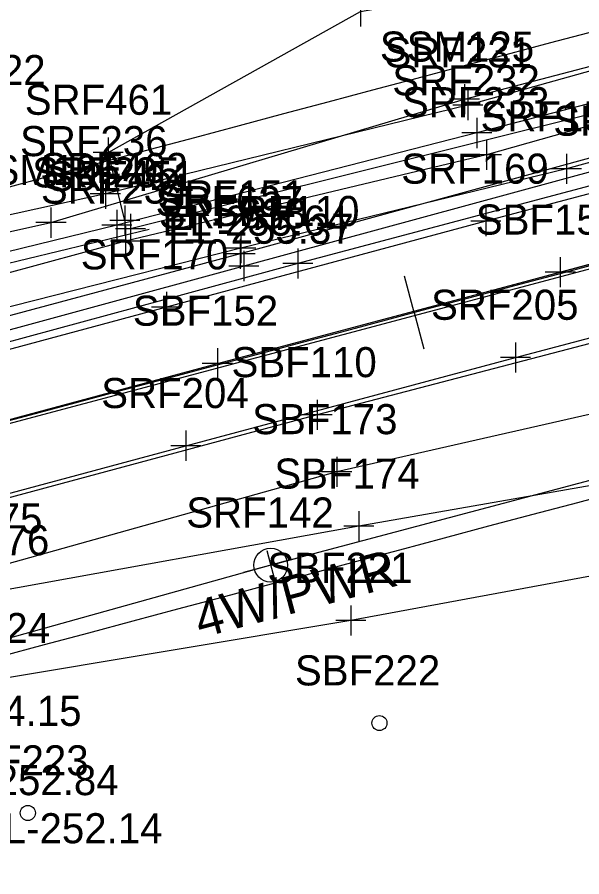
# Model space of a CAD drawing. Extents: x 818717 to 846077, y 440014 to 541392.
# Drawn here: x 831874.2 to 831949.3, y 493090.2 to 493204.5 of the extents above; entities that cross this region are included whole.
import ezdxf

# ---------------------------------------------------------------- set-up
doc = ezdxf.new("R2010")
doc.units = 0
for name, color, linetype in [('SURVEY - CENTERLINE - Preliminary', 7, 'Continuous'), ('SURVEY - CENTERLINE - Preliminary Text', 7, 'Continuous'), ('SURVEY - DRAINAGE - Area Shapes', 7, 'Continuous'), ('SURVEY - DRAINAGE - Natural Features Text', 7, 'Continuous'), ('SURVEY - DTM - Breaklines', 7, 'Continuous'), ('SURVEY - DTM - Breaklines - Points - Elevations', 7, 'Continuous'), ('SURVEY - DTM - Breaklines - Points - Locators', 7, 'Continuous'), ('SURVEY - DTM - Breaklines - Points - Numbers', 7, 'Continuous'), ('SURVEY - DTM - Spot Points - Locators', 7, 'Continuous'), ('SURVEY - DTM - Spot Points - Point Numbers', 7, 'Continuous'), ('SURVEY - PROPERTY - ROW Lines', 7, 'Continuous'), ('SURVEY - TRAFFIC CONTROL - Pavement Marking - Points - Locators', 7, 'Continuous'), ('SURVEY - TRAFFIC CONTROL - Pavement Marking - Points - Numbers', 7, 'Continuous'), ('SURVEY - TRAFFIC CONTROL - Pavement Marking with Text', 7, 'Continuous'), ('SURVEY - TRANSPORTATION - Features - Points - Elevations', 7, 'Continuous'), ('SURVEY - TRANSPORTATION - Roads', 7, 'Continuous'), ('SURVEY - TRANSPORTATION - Roads - Points - Locators', 7, 'Continuous'), ('SURVEY - TRANSPORTATION - Roads - Points - Numbers', 7, 'Continuous'), ('SURVEY - UTILITIES - Electric (Overhead) with Text', 7, 'Continuous'), ('SURVEY - UTILITIES - Poles and Miscellaneous - Points - Locators', 7, 'Continuous'), ('SURVEY - UTILITIES - Poles and Miscellaneous - Points - Numbers', 7, 'Continuous'), ('SURVEY - UTILITIES - Poles and Miscellaneous with Text', 7, 'Continuous'), ('SURVEY - UTILITIES - Telephone (Underground) - Points - Locators', 7, 'Continuous'), ('SURVEY - UTILITIES - Telephone (Underground) - Points - Numbers', 7, 'Continuous'), ('SURVEY - UTILITIES - Telephone (Underground) with Text', 7, 'Continuous'), ('SURVEY - UTILITIES - Water - Points - Locators', 7, 'Continuous'), ('SURVEY - UTILITIES - Water - Points - Numbers', 7, 'Continuous'), ('SURVEY - UTILITIES - Water with Text', 7, 'Continuous'), ('SURVEY - VEGETATION - Features - Points - Elevations', 7, 'Continuous'), ('SURVEY - VEGETATION - Features - Points - Locators', 7, 'Continuous'), ('SURVEY - VEGETATION - Features - Points - Numbers', 7, 'Continuous'), ('SURVEY - VEGETATION - Features with Text', 7, 'Continuous')]:
    doc.layers.add(name, color=color, linetype=linetype)

msp = doc.modelspace()

# ---------------------------------------------------------------- linework, layer by layer
at = {"layer": 'SURVEY - CENTERLINE - Preliminary'}
msp.add_arc((846074.62, 440015.93), 55000, 104.635499, 105.043654, dxfattribs=at)
msp.add_arc((846074.62, 440015.93), 55000, 104.635499, 105.043654, dxfattribs=at)
msp.add_arc((846074.62, 440015.93), 55000, 104.635499, 105.043654, dxfattribs=at)
at = {"layer": 'SURVEY - CENTERLINE - Preliminary Text'}
for p, q in [((831940, 493168.86), (831988.29, 493181.84)), ((831927.05, 493165.22), (831925.77, 493170.05)), ((831927.05, 493165.22), (831928.34, 493160.39))]:
    msp.add_line(p, q, dxfattribs=at)
at = {"layer": 'SURVEY - DRAINAGE - Area Shapes'}
msp.add_lwpolyline([(833331.86, 493535.43), (832825.85, 493400.54), (832121.68, 493216.64), (831495.16, 493049.75), (830960.37, 492909.24), (830124.73, 492686.08), (830069.9, 493396.23), (830870.86, 494031.84), (831248.11, 494413.67), (831536.95, 494545.33), (832050.07, 494534.01), (832097.96, 494614.84), (832139.36, 494784.62), (832167.46, 494840.58), (832274.31, 494844.36), (832647.22, 494804.13), (832934.24, 494910.41), (833081.03, 494456.05), (833331.86, 493535.43)], dxfattribs=at)
at = {"layer": 'SURVEY - DRAINAGE - Natural Features Text'}
msp.add_line((831853.84, 493167.16), (831891.8, 493176.31), dxfattribs=at)
at = {"layer": 'SURVEY - DTM - Breaklines'}
for points in [[(831770.96, 493123.4), (831813.86, 493135.07), (831857.39, 493146.73), (831900.86, 493158.47), (831946.48, 493170.59), (831992.71, 493182.98), (832039.15, 493195.18), (832084.76, 493206.97), (832129.99, 493218.78), (832149.29, 493223.98), (832194.39, 493235.62), (832247.61, 493249.75), (832293.49, 493261.68), (832340.52, 493273.78)], [(832142.59, 493248.12), (832139.68, 493247.54), (832108.04, 493238.25), (832059.21, 493226.8), (832016.93, 493214.13), (831977.53, 493204.88), (831934.18, 493192.82), (831885.96, 493181.02), (831841.41, 493171.23), (831796.37, 493166.38), (831801.69, 493181.68), (831795.28, 493183.83), (831789.32, 493168.76), (831775.78, 493173.56), (831765.85, 493166.76)], [(832140.22, 493244.36), (832106.95, 493233.7), (832060.11, 493221.66), (832022.66, 493211.6), (831981.44, 493201.09), (831935.37, 493189.1), (831887.47, 493176.86), (831843.25, 493166.04), (831798.12, 493162.94), (831794.2, 493164.7), (831799.41, 493178.67), (831795.65, 493181.96), (831790.41, 493167.38)], [(832140.95, 493241.96), (832107.3, 493230.3), (832060.96, 493218.28), (832023.31, 493209.39), (831981.76, 493198.9), (831936.65, 493186.2), (831888.63, 493174.71), (831844.24, 493162.67), (831795, 493159.67)], [(832140.88, 493237.3), (832107.45, 493226.49), (832065.3, 493215.2), (832029.04, 493206.5), (831988.85, 493195.72), (831947.28, 493184.33), (831903.99, 493173.8), (831854.37, 493161.21), (831813.24, 493150.7), (831784.54, 493147.95), (831766.05, 493144.17), (831768.61, 493132.98)], [(832195.49, 493218.96), (832149.66, 493208), (832104.44, 493192.76), (832056.4, 493179.89), (832008.79, 493165.69), (831963, 493154.57), (831916.73, 493144.05), (831869.5, 493130.85), (831832.06, 493121.28), (831826.36, 493121.02)], [(832151.95, 493201.02), (832107.01, 493186.71), (832059.04, 493168.48), (832010.73, 493158.07), (831966.04, 493144.93), (831919.68, 493136.81), (831870.53, 493127.95), (831847.89, 493115.55), (831850.33, 493110.02), (831858.04, 493103.05), (831863.88, 493096.65)], [(832157.93, 493179.81), (832105.79, 493168.96), (832054.16, 493155.49), (832007.33, 493148.26), (831961.05, 493132.11), (831918.6, 493124.28), (831870.52, 493116.27), (831853.11, 493112.26), (831850.33, 493110.02)]]:
    msp.add_lwpolyline(points, dxfattribs=at)
at = {"layer": 'SURVEY - DTM - Breaklines - Points - Locators'}
for p, q in [((831934.18, 493194.82), (831934.18, 493190.82)), ((831936.18, 493192.82), (831932.18, 493192.82)), ((831935.37, 493191.1), (831935.37, 493187.1)), ((831937.37, 493189.1), (831933.37, 493189.1)), ((831936.65, 493188.2), (831936.65, 493184.2)), ((831938.65, 493186.2), (831934.65, 493186.2)), ((831947.28, 493186.33), (831947.28, 493182.33)), ((831949.28, 493184.33), (831945.28, 493184.33)), ((831885.96, 493183.02), (831885.96, 493179.02)), ((831887.96, 493181.02), (831883.96, 493181.02)), ((831887.47, 493178.86), (831887.47, 493174.86)), ((831889.47, 493176.86), (831885.47, 493176.86)), ((831888.63, 493176.71), (831888.63, 493172.71)), ((831903.99, 493175.8), (831903.99, 493171.8)), ((831890.63, 493174.71), (831886.63, 493174.71)), ((831905.99, 493173.8), (831901.99, 493173.8)), ((831946.48, 493172.59), (831946.48, 493168.59)), ((831948.48, 493170.59), (831944.48, 493170.59)), ((831900.86, 493160.47), (831900.86, 493156.47)), ((831902.86, 493158.47), (831898.86, 493158.47)), ((831916.73, 493146.05), (831916.73, 493142.05)), ((831918.73, 493144.05), (831914.73, 493144.05)), ((831919.68, 493138.81), (831919.68, 493134.81)), ((831921.68, 493136.81), (831917.68, 493136.81)), ((831918.6, 493126.28), (831918.6, 493122.28)), ((831920.6, 493124.28), (831916.6, 493124.28))]:
    msp.add_line(p, q, dxfattribs=at)
at = {"layer": 'SURVEY - DTM - Spot Points - Locators'}
for centre in [(831922.42, 493110.64), (831875.65, 493098.68)]:
    msp.add_circle(centre, 1, dxfattribs=at)
at = {"layer": 'SURVEY - PROPERTY - ROW Lines'}
for radius in [55030, 54970]:
    msp.add_arc((846074.62, 440015.93), radius, 104.635499, 105.043649, dxfattribs=at)
at = {"layer": 'SURVEY - TRAFFIC CONTROL - Pavement Marking - Points - Locators'}
for p, q in [((831936.58, 493179.36), (831936.58, 493175.36)), ((831938.58, 493177.36), (831934.58, 493177.36)), ((831894.1, 493167.96), (831894.1, 493163.96)), ((831896.1, 493165.96), (831892.1, 493165.96)), ((831940.52, 493161.26), (831940.52, 493157.26)), ((831942.52, 493159.26), (831938.52, 493159.26)), ((831896.65, 493149.52), (831896.65, 493145.52)), ((831898.65, 493147.52), (831894.65, 493147.52))]:
    msp.add_line(p, q, dxfattribs=at)
at = {"layer": 'SURVEY - TRAFFIC CONTROL - Pavement Marking with Text'}
for points in [[(832159.39, 493235.77), (832116.7, 493224.52), (832072.63, 493213.17), (832030, 493201.97), (831987.46, 493190.83), (831936.58, 493177.36), (831894.1, 493165.96), (831849.46, 493153.92), (831808.03, 493142.52), (831768.36, 493131.66), (831727.87, 493120.89), (831684.5, 493109.18), (831641.68, 493097.86), (831599.16, 493086.58), (831554.58, 493074.61), (831511.86, 493063.5), (831467.07, 493051.66), (831425.05, 493040.69), (831380.34, 493029.11), (831337.84, 493017.82), (831296.13, 493006.89), (831251.61, 492995.36), (831208.94, 492984.12), (831169.87, 492973.88)], [(831174.64, 492955.97), (831217.88, 492967.4), (831260.2, 492978.43), (831305.6, 492990.16), (831350.87, 493002.2), (831397.34, 493014.25), (831441.59, 493025.83), (831487.77, 493037.91), (831534.41, 493050.33), (831587.19, 493064.38), (831630.52, 493075.92), (831676.82, 493088.3), (831723.86, 493100.96), (831758.43, 493110.25), (831806.28, 493123.18), (831848.98, 493134.67), (831896.65, 493147.52), (831940.52, 493159.26), (831989.17, 493172.11), (832037.06, 493184.69), (832086.82, 493197.77), (832134.83, 493210.3)]]:
    msp.add_lwpolyline(points, dxfattribs=at)
at = {"layer": 'SURVEY - TRANSPORTATION - Roads'}
for points in [[(832337.43, 493283.54), (832290.84, 493271.51), (832245.1, 493259.5), (832196.72, 493246.64), (832147.48, 493233.5), (832099.04, 493220.81), (832050.97, 493208.2), (832002.93, 493195.99), (831956.8, 493183.74), (831911.55, 493171.73), (831864.83, 493159.08), (831817.3, 493145.76), (831768.68, 493132.69)], [(832342.92, 493264.27), (832295.67, 493251.85), (832250.01, 493239.95), (832200.63, 493227.05), (832152.17, 493214.17), (832103.93, 493201.62), (832054.77, 493188.77), (832008.06, 493176.05), (831961.15, 493163.88), (831914.15, 493151.63), (831865.83, 493138.65), (831819.22, 493125.71), (831773.59, 493113.35)]]:
    msp.add_lwpolyline(points, dxfattribs=at)
at = {"layer": 'SURVEY - TRANSPORTATION - Roads - Points - Locators'}
for p, q in [((831911.55, 493173.73), (831911.55, 493169.73)), ((831913.55, 493171.73), (831909.55, 493171.73)), ((831914.15, 493153.63), (831914.15, 493149.63)), ((831916.15, 493151.63), (831912.15, 493151.63))]:
    msp.add_line(p, q, dxfattribs=at)
at = {"layer": 'SURVEY - UTILITIES - Electric (Overhead) with Text'}
msp.add_lwpolyline([(832667.18, 493331.74), (832415.28, 493266.23), (832147.85, 493195.27), (831907.96, 493131.64), (831666.03, 493064.14), (831375.19, 492986.65), (831101.3, 492913.04)], dxfattribs=at)
at = {"layer": 'SURVEY - UTILITIES - Poles and Miscellaneous - Points - Locators'}
for p, q in [((831907.45, 493133.57), (831908.48, 493129.71)), ((831909.89, 493132.15), (831906.03, 493131.12))]:
    msp.add_line(p, q, dxfattribs=at)
at = {"layer": 'SURVEY - UTILITIES - Poles and Miscellaneous with Text'}
for q in [(831904.34, 493130.67), (831911.58, 493132.61)]:
    msp.add_line((831907.96, 493131.64), q, dxfattribs=at)
msp.add_circle((831907.96, 493131.64), 2.25, dxfattribs=at)
at = {"layer": 'SURVEY - UTILITIES - Telephone (Underground) - Points - Locators'}
for p, q in [((831903.88, 493175.04), (831903.88, 493171.04)), ((831905.88, 493173.04), (831901.88, 493173.04)), ((831904.38, 493173.41), (831904.38, 493169.41)), ((831906.38, 493171.41), (831902.38, 493171.41))]:
    msp.add_line(p, q, dxfattribs=at)
at = {"layer": 'SURVEY - UTILITIES - Telephone (Underground) with Text'}
for points in [[(832336.84, 493284.72), (832273.67, 493269.41), (832254.65, 493265.33), (832241.32, 493260.67), (832203.09, 493249.29), (832136.87, 493232.13), (832079.02, 493217.89), (831981.8, 493192.44), (831904.38, 493171.41), (831843.31, 493154.78), (831799.38, 493142.99), (831790.74, 493148.24), (831757.75, 493149.99)], [(832214.24, 493268.88), (832214.09, 493255.37), (832202.72, 493250.84), (832136.43, 493233.69), (832079.13, 493219.64), (831981.43, 493194.27), (831903.88, 493173.04), (831842.73, 493156.61), (831799.25, 493144.57), (831792.09, 493149.13), (831757.2, 493152.41)]]:
    msp.add_lwpolyline(points, dxfattribs=at)
at = {"layer": 'SURVEY - UTILITIES - Water - Points - Locators'}
for p, q in [((831933.72, 493195.59), (831933.72, 493191.59)), ((831935.72, 493193.59), (831931.72, 493193.59)), ((831878.73, 493179.18), (831878.73, 493175.18)), ((831880.73, 493177.18), (831876.73, 493177.18))]:
    msp.add_line(p, q, dxfattribs=at)
at = {"layer": 'SURVEY - UTILITIES - Water with Text'}
msp.add_lwpolyline([(831168.53, 492982.83), (831221.68, 492997.59), (831271.35, 493010.03), (831320.05, 493023.02), (831382.11, 493039.09), (831464.43, 493059.02), (831521.6, 493075.98), (831637.27, 493105.47), (831699.54, 493130.69), (831734.63, 493142.29), (831763.92, 493149.4), (831800.53, 493157.83), (831844.47, 493169.57), (831878.73, 493177.18), (831933.72, 493193.59), (832000.95, 493211.25), (832058.59, 493225.48), (832113.6, 493238.29), (832172.68, 493261.93), (832217.98, 493273.66), (832269.17, 493287.2), (832330.79, 493299.45)], dxfattribs=at)
at = {"layer": 'SURVEY - VEGETATION - Features - Points - Locators'}
for p, q in [((831919.88, 493207.25), (831919.88, 493203.25)), ((831886.32, 493188.52), (831886.32, 493184.52)), ((831888.32, 493186.52), (831884.32, 493186.52)), ((831888.55, 493179.45), (831888.55, 493175.45)), ((831890.55, 493177.45), (831886.55, 493177.45)), ((831889.31, 493178.37), (831889.31, 493174.37)), ((831891.31, 493176.37), (831887.31, 493176.37))]:
    msp.add_line(p, q, dxfattribs=at)
at = {"layer": 'SURVEY - VEGETATION - Features with Text'}
msp.add_lwpolyline([(831888.55, 493177.45), (831886.32, 493186.52), (831919.88, 493205.25), (831958.38, 493211.98), (831995.55, 493226.97), (832045.5, 493254.8), (832112.46, 493247.88), (832111.49, 493228.36), (832055.54, 493211.96), (832015.77, 493204.39), (831965.98, 493195.44), (831889.31, 493176.37)], dxfattribs=at)

# ---------------------------------------------------------------- texts
at = {"layer": 'SURVEY - DTM - Breaklines - Points - Elevations'}
for s, p in [('EL-254.15', (831858.11, 493110.26)), ('EL-252.84', (831863.04, 493101.05))]:
    msp.add_text(s, height=4, dxfattribs=at).set_placement(p)
at = {"layer": 'SURVEY - DTM - Breaklines - Points - Numbers'}
for s, p in [('SRF231', (831923.1, 493197.82)), ('SRF232', (831924.13, 493194.1)), ('SRF233', (831925.41, 493191.2)), ('SRF150', (831935.87, 493189.33)), ('SRF236', (831874.61, 493186.02)), ('SRF235', (831876.23, 493181.86)), ('SRF234', (831877.39, 493179.71)), ('SRF151', (831892.91, 493178.8)), ('SBF153', (831935.24, 493175.59)), ('SBF152', (831889.62, 493163.47)), ('SBF173', (831905.49, 493149.05)), ('SBF174', (831908.44, 493141.81)), ('SBF175', (831858.26, 493135.85)), ('SBF176', (831859.18, 493132.95)), ('SBF221', (831907.51, 493129.28)), ('SBF224', (831859.28, 493121.27))]:
    msp.add_text(s, height=4, dxfattribs=at).set_placement(p)
at = {"layer": 'SURVEY - DTM - Spot Points - Point Numbers'}
for s, p in [('SRF422', (831858.39, 493195.47)), ('SBF222', (831911.18, 493115.64)), ('SBF223', (831864.41, 493103.68))]:
    msp.add_text(s, height=4, dxfattribs=at).set_placement(p)
at = {"layer": 'SURVEY - TRAFFIC CONTROL - Pavement Marking - Points - Numbers'}
for s, p in [('SRF169', (831925.32, 493182.36)), ('SRF170', (831882.69, 493170.96)), ('SRF205', (831929.28, 493164.26)), ('SRF204', (831885.41, 493152.52))]:
    msp.add_text(s, height=4, dxfattribs=at).set_placement(p)
at = {"layer": 'SURVEY - TRANSPORTATION - Features - Points - Elevations'}
msp.add_text('EL-252.14', height=4, dxfattribs=at).set_placement((831868.88, 493094.65))
at = {"layer": 'SURVEY - TRANSPORTATION - Roads - Points - Numbers'}
for s, p in [('SRF109', (831945.55, 493188.74)), ('SRF110', (831900.14, 493176.73)), ('SBF110', (831902.74, 493156.63))]:
    msp.add_text(s, height=4, dxfattribs=at).set_placement(p)
at = {"layer": 'SURVEY - UTILITIES - Electric (Overhead) with Text'}
msp.add_text('4W/PWR', height=5, rotation=14.9282, dxfattribs=at).set_placement((831898.6, 493121.91))
at = {"layer": 'SURVEY - UTILITIES - Poles and Miscellaneous - Points - Numbers'}
msp.add_text('SRF142', height=4, dxfattribs=at).set_placement((831896.72, 493136.64))
at = {"layer": 'SURVEY - UTILITIES - Telephone (Underground) - Points - Numbers'}
for s, p in [('SRF637', (831892.64, 493178.04)), ('SRF638', (831893.09, 493176.41))]:
    msp.add_text(s, height=4, dxfattribs=at).set_placement(p)
at = {"layer": 'SURVEY - UTILITIES - Water - Points - Numbers'}
for s, p in [('SSM125', (831922.48, 493198.59)), ('SSM126', (831867.38, 493182.18))]:
    msp.add_text(s, height=4, dxfattribs=at).set_placement(p)
at = {"layer": 'SURVEY - VEGETATION - Features - Points - Elevations'}
for s, p in [('EL-255.64', (831893.55, 493175.45)), ('EL-255.37', (831894.31, 493174.37))]:
    msp.add_text(s, height=4, dxfattribs=at).set_placement(p)
at = {"layer": 'SURVEY - VEGETATION - Features - Points - Numbers'}
for s, p in [('SRF461', (831875.24, 493191.52)), ('SRF462', (831877.31, 493182.45)), ('SRF451', (831878.23, 493181.37))]:
    msp.add_text(s, height=4, dxfattribs=at).set_placement(p)

doc.saveas('drawing.dxf')
